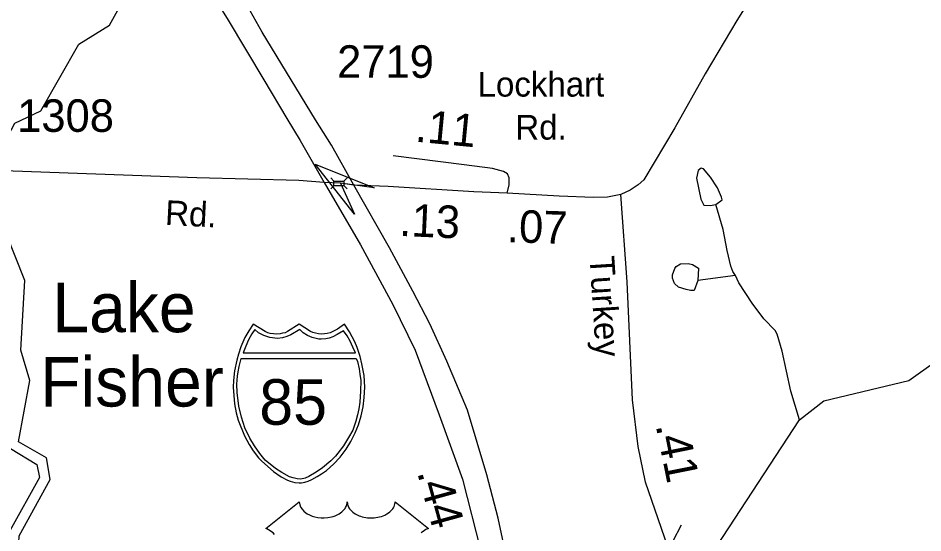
# Model space of a CAD drawing. Extents: x 1473865 to 1648260, y 639067 to 773536.
# Drawn here: x 1533158 to 1536635, y 642600 to 644578 of the extents above; entities that cross this region are included whole.
import ezdxf

# ---------------------------------------------------------------- set-up
doc = ezdxf.new("R2010")
doc.units = 0
for name, color, linetype in [('Exist Hydrographic Buffer Line', 7, 'Continuous'), ('Exist Hydrographic Creek Single Shore', 7, 'Continuous'), ('Exist Hydrographic Lake Shore', 7, 'Continuous'), ('Exist Hydrographic Lake Shore Label', 7, 'Continuous'), ('Exist Hydrographic Misc Water Feature', 7, 'Continuous'), ('Exist Road Primary Interstate Divided Center Attributed', 7, 'Continuous'), ('Exist Road Primary Interstate Mileage Hundredths English Label', 7, 'Continuous'), ('Exist Road Primary Interstate Shield CELL', 7, 'Continuous'), ('Exist Road Primary Interstate Shield Number Label', 7, 'Continuous'), ('Exist Road Primary US Shield CELL', 7, 'Continuous'), ('Exist Road Secondary Mileage Hundredths English Label', 7, 'Continuous'), ('Exist Road Secondary Structure Standard Bridge Attributed CELL', 7, 'Continuous'), ('Exist Road Secondary Structure Standard Bridge CELL', 7, 'Continuous'), ('Exist Road Secondary Type 51 Attributed', 7, 'Continuous'), ('Exist Road Secondary Type 51 Label', 7, 'Continuous'), ('Exist Road Secondary Type 51 Number Label', 7, 'Continuous')]:
    doc.layers.add(name, color=color, linetype=linetype)

msp = doc.modelspace()

# ---------------------------------------------------------------- linework, layer by layer
at = {"layer": 'Exist Hydrographic Buffer Line'}
msp.add_lwpolyline([(1533129.2, 642924.1), (1533230.8, 642863), (1533239.9, 642813), (1533126.9, 642608)], dxfattribs=at)
at = {"layer": 'Exist Hydrographic Creek Single Shore'}
for points in [[(1533145.9, 644174.4), (1533245.9, 644221.6), (1533391.9, 644477.9), (1533509.9, 644551.1), (1533586.9, 644690.7), (1533679.9, 644757.8), (1534047.8, 644842.2), (1534114.9, 644883.5), (1534310.9, 645122.5), (1534478.9, 645243.8), (1534666.9, 645476.4), (1534979.9, 645788.5), (1535526, 646046.6)], [(1536254.9, 643107.3), (1536580.9, 643186), (1536682.9, 643259.5), (1536786.3, 643339), (1536946.2, 643460.5), (1537173.9, 643751.8), (1537348.9, 643948.4), (1537493.2, 644144.8), (1537550.6, 644125.3), (1537590.8, 644111.1), (1537644.6, 644123.4), (1537654.1, 644129.7), (1537717.6, 644182.4), (1537698.9, 644286.1), (1537837.9, 644624.6), (1537981, 644713.7), (1538125.9, 644930.7), (1538234.9, 644987.6), (1538335, 645002), (1538509.9, 644939.3), (1538789, 644700.7), (1539004.9, 644624.1), (1539113, 644437.9)], [(1535821.8, 642516.4), (1536160.3, 643034.5), (1536254.9, 643107.3)]]:
    msp.add_lwpolyline(points, dxfattribs=at)
at = {"layer": 'Exist Hydrographic Lake Shore'}
msp.add_lwpolyline([(1533466.8, 641843.9), (1533442.8, 641867.4), (1533142.8, 641873.5), (1533049.9, 641826), (1532974.8, 641844), (1532967.8, 641932.8), (1533078.9, 642097.9), (1533149.8, 642332.8), (1533161.8, 642588.6), (1533281.9, 642806.1), (1533266.9, 642888.5), (1533159.9, 642949.8), (1533203.9, 643186.6), (1533168.5, 643302), (1533184.1, 643570.3), (1533111.9, 643751), (1533081.4, 643851), (1533050.8, 643978.9), (1532828.6, 643987.2), (1532834.9, 644062.5), (1533119.9, 644125.7), (1533145.9, 644174.4)], dxfattribs=at)
at = {"layer": 'Exist Hydrographic Misc Water Feature'}
msp.add_line((1535914.8, 643589.2), (1535770.7, 643570.8), dxfattribs=at)
for points in [[(1535839.1, 643862.4), (1535863.5, 643879.9), (1535861.6, 643889.8), (1535846.2, 643926.2), (1535818.9, 643967), (1535791.4, 643998.8), (1535783.4, 644001.4), (1535771.2, 643993.4), (1535764.9, 643963.2), (1535781.5, 643883.2), (1535793, 643859.2), (1535817, 643858.7), (1535839.1, 643862.4)], [(1535914.8, 643589.2), (1535905.1, 643605), (1535897.5, 643624.9), (1535882.3, 643685.9), (1535867.7, 643765.8), (1535839.1, 643862.4)], [(1535770.7, 643570.8), (1535755.9, 643531.7), (1535742, 643532), (1535726, 643535.6), (1535696.1, 643544.4), (1535680.4, 643558.7), (1535672.6, 643578.5), (1535672.8, 643592.5), (1535681.3, 643616.9), (1535687.4, 643624.2), (1535703.6, 643634.6), (1535733.6, 643635.6), (1535749.6, 643632), (1535773.3, 643617.5), (1535770.7, 643570.8)], [(1536160.3, 643034.5), (1536128, 643145.1), (1536094.4, 643298.4), (1536075.4, 643364.4), (1536067.7, 643378.5), (1536024.3, 643422.9), (1535979.1, 643483.7), (1535928.4, 643561.1), (1535914.8, 643589.2)]]:
    msp.add_lwpolyline(points, dxfattribs=at)
at = {"layer": 'Exist Road Primary Interstate Divided Center Attributed'}
for points in [[(1532067.3, 650189.8), (1532099.1, 649959.9), (1532111.6, 649897), (1532259.9, 649188.3), (1532318.9, 648953.8), (1532471.4, 648352.8), (1532570.8, 647967.9), (1532653.9, 647677.9), (1532722.1, 647429.7), (1532805, 647156.8), (1532938.2, 646804.3), (1533038.9, 646486.3), (1533121.3, 646291.5), (1533241.4, 645985.6), (1533539.8, 645344.6), (1533565.9, 645296.1), (1533841.5, 644771), (1533965.2, 644570.1), (1534102.5, 644341.3), (1534190.9, 644192.8), (1534242.1, 644107.9), (1534333.9, 643947.3)], [(1534448.8, 643936.4), (1534362.3, 644090.3), (1534300.4, 644187.5), (1534095.9, 644524.2), (1533991.7, 644709.8), (1533727.1, 645173.1), (1533476.4, 645676.2), (1533317.4, 646052.8), (1533114.9, 646555.3), (1533102.8, 646630.2), (1532913.8, 647168.1), (1532841.1, 647408.6), (1532674.2, 647927.5), (1532602.5, 648225.7), (1532357.1, 649178), (1532309.8, 649428.6), (1532208.2, 649864.6), (1532194.5, 649938.7), (1532161, 650159.7)], [(1534333.9, 643947.3), (1534473.6, 643706.6), (1534598.7, 643478.1), (1534683.6, 643303), (1534776.1, 643054.7), (1534865.6, 642806.9), (1534936.8, 642529.8), (1534978.3, 642275), (1535004.4, 642062.6), (1535011.1, 641823.7), (1535003.1, 641707.2)], [(1535103.8, 641702.9), (1535099.8, 641843.1), (1535091.6, 642021), (1535038.5, 642489), (1535003.2, 642656.5), (1534959.2, 642823.8), (1534885, 643071.4), (1534806, 643260.5), (1534740.5, 643403.7), (1534674.8, 643528.6), (1534584.9, 643695.9), (1534448.8, 643936.4)]]:
    msp.add_lwpolyline(points, dxfattribs=at)
at = {"layer": 'Exist Road Primary Interstate Shield CELL'}
for points in [[(1534237.9, 642792.2), (1534247.3, 642793.1), (1534260.1, 642795.6), (1534272.5, 642799.7), (1534286.6, 642805.9), (1534307.4, 642817.4), (1534324.2, 642827.3), (1534343.5, 642840.3), (1534369.6, 642864), (1534395.7, 642891.4), (1534418.7, 642922.4), (1534436.9, 642951.4), (1534453, 642984.6), (1534466.4, 643015.5), (1534477.1, 643050.8), (1534484.2, 643085.1), (1534487.7, 643120.8), (1534490.1, 643160.3), (1534487.4, 643204.9), (1534479.7, 643250.4), (1534472.4, 643278.8), (1534461.4, 643312.7), (1534452.4, 643334.4), (1534431.5, 643372.8), (1534412.8, 643402.4), (1534385.6, 643383.3), (1534367.8, 643373.8), (1534357, 643369), (1534345.8, 643366.8), (1534325.3, 643364.3), (1534312.4, 643364.9), (1534300.5, 643367.6), (1534290.4, 643369.8), (1534282.1, 643373.8), (1534237.9, 643402.4), (1534193.6, 643373.8), (1534184.3, 643369.6), (1534174.8, 643367.6), (1534165.7, 643365.1), (1534150.5, 643364.3), (1534139, 643364.7), (1534127.1, 643366.8), (1534117.7, 643368.8), (1534107.2, 643373.8), (1534062.1, 643402.4), (1534044.4, 643376.7), (1534029.9, 643351.3), (1534014.5, 643315.4), (1534005, 643287.6), (1533998.2, 643264.7), (1533989.8, 643222.7), (1533985.5, 643186.2), (1533984.8, 643160.3), (1533989.5, 643095.8), (1533996.5, 643061.5), (1534003.8, 643033.7), (1534027.6, 642973.6), (1534045.6, 642940), (1534061, 642915.9), (1534082.6, 642888.7), (1534094.3, 642875.7), (1534139.1, 642836.6), (1534169, 642816.1), (1534192.9, 642803.2), (1534204.1, 642798.9), (1534221.7, 642794)], [(1534067.4, 643381.7), (1534056.5, 643364.8), (1534043.8, 643341.9), (1534033.6, 643318.3), (1534023.3, 643292.1), (1534454.8, 643292), (1534444.8, 643314.4), (1534434, 643336.9), (1534422.8, 643357.5), (1534409.1, 643377.4), (1534384.9, 643362.1), (1534367.2, 643353.8), (1534353.1, 643348.9), (1534341.1, 643346.2), (1534322.5, 643344.7), (1534314.2, 643345.2), (1534288.2, 643351.1), (1534270.7, 643358.3), (1534254, 643369.4), (1534240.5, 643382.1), (1534206.3, 643361.5), (1534191.1, 643354.8), (1534173.6, 643350.3), (1534154.6, 643347.9), (1534125.1, 643351.1), (1534102.1, 643359.1), (1534082.2, 643369.4)], [(1534457.4, 643270.7), (1534462, 643258.5), (1534468.4, 643231.4), (1534471.7, 643210.6), (1534475.1, 643186.6), (1534473.9, 643145.5), (1534472, 643102.9), (1534468, 643077.7), (1534462.8, 643054.7), (1534455.6, 643029.3), (1534444.1, 642995.4), (1534428.2, 642966.8), (1534408.3, 642935), (1534386.9, 642907.1), (1534377.5, 642895.5), (1534359.8, 642876.9), (1534327.6, 642851), (1534304.1, 642833.4), (1534275.9, 642816.8), (1534261.6, 642810.4), (1534244.9, 642806.9), (1534231.2, 642807.9), (1534214.6, 642812.3), (1534201.1, 642816), (1534171.7, 642831.9), (1534147.9, 642847.8), (1534108.1, 642880.4), (1534086.6, 642905.6), (1534066.6, 642934.9), (1534048.7, 642965), (1534029.6, 643004.7), (1534016.2, 643044.6), (1534006.4, 643087.7), (1533999.8, 643140.3), (1533999.1, 643172.4), (1534001, 643203.2), (1534004, 643219.4), (1534007.9, 643239.5), (1534015.7, 643270.4)]]:
    msp.add_lwpolyline(points, close=True, dxfattribs=at)
at = {"layer": 'Exist Road Primary US Shield CELL'}
msp.add_lwpolyline([(1534143.5, 642594.8), (1534137.8, 642600.5), (1534132.3, 642604.8), (1534127.1, 642608.5), (1534120.6, 642612.5), (1534114.3, 642615.6), (1534110.3, 642617.2), (1534238.9, 642719.6), (1534239.2, 642714.3), (1534240.5, 642708), (1534241.5, 642704.7), (1534244.5, 642698.5), (1534249.3, 642691.1), (1534256.1, 642683.9), (1534263.8, 642677.6), (1534269, 642674.2), (1534277.7, 642669.5), (1534287.7, 642665.3), (1534298.8, 642662.2), (1534310.1, 642659.9), (1534322.5, 642658.5), (1534334.7, 642658.3), (1534347.9, 642659.3), (1534362.5, 642662.1), (1534369.2, 642663.8), (1534376.8, 642666.4), (1534383.8, 642669.3), (1534391.4, 642673.4), (1534397.6, 642677.4), (1534402.4, 642680.8), (1534409.2, 642687.4), (1534414.7, 642694.1), (1534416.9, 642697.9), (1534418.9, 642701.6), (1534421.6, 642709.3), (1534422.4, 642712.8), (1534422.9, 642719.9), (1534423.4, 642713.9), (1534424, 642710.2), (1534425, 642706.5), (1534426.5, 642702.7), (1534429.2, 642697.2), (1534432.2, 642692.6), (1534438, 642685.9), (1534441.5, 642682.5), (1534444.8, 642679.9), (1534453.5, 642673.9), (1534463.8, 642668.7), (1534468.8, 642666.5), (1534473.9, 642664.7), (1534480.5, 642662.7), (1534487.2, 642661.1), (1534493.9, 642660), (1534500.7, 642659), (1534507.7, 642658.4), (1534513.4, 642658.3), (1534520.4, 642658.4), (1534526.9, 642658.7), (1534533.5, 642659.5), (1534540.8, 642660.7), (1534546.6, 642662), (1534554.4, 642664.1), (1534561.4, 642666.6), (1534567.5, 642669.2), (1534575.5, 642673.4), (1534581.9, 642677.4), (1534586.7, 642681.2), (1534592.3, 642686.4), (1534597.6, 642692.6), (1534600.7, 642697), (1534602.9, 642701.7), (1534605, 642706.5), (1534606.2, 642711.7), (1534606.8, 642716.2), (1534606.9, 642720), (1534735.5, 642617.6), (1534732.5, 642616.4), (1534725.5, 642613), (1534720, 642609.7), (1534711.1, 642603.5), (1534707.3, 642600.1)], dxfattribs=at)
at = {"layer": 'Exist Road Secondary Structure Standard Bridge Attributed CELL'}
msp.add_lwpolyline([(1534450.7, 643824.9), (1534300, 644016.6), (1534526.4, 643925.9), (1534397.6, 643943.5)], close=True, dxfattribs=at)
at = {"layer": 'Exist Road Secondary Structure Standard Bridge CELL'}
for p, q in [((1534359.9, 643964.1), (1534372.1, 643951.9)), ((1534409.9, 643951.8), (1534422.1, 643964)), ((1534359.9, 643922), (1534372.1, 643934.2)), ((1534409.9, 643934.5), (1534422.1, 643922.3)), ((1535676, 642569.6), (1535706.9, 642631.3))]:
    msp.add_line(p, q, dxfattribs=at)
msp.add_lwpolyline([(1534372.1, 643951.9), (1534409.9, 643951.9), (1534409.9, 643934.2), (1534372.1, 643934.2)], close=True, dxfattribs=at)
at = {"layer": 'Exist Road Secondary Type 51 Attributed'}
for points in [[(1536846.3, 645558.6), (1536759.1, 645492.3), (1536578.3, 645352.6), (1536423.9, 645210.7), (1536271.6, 645062.7), (1536131.8, 644906.5), (1535919.8, 644569.2), (1535798, 644364), (1535682.3, 644156.4), (1535562.6, 643956.3), (1535540.4, 643937.5), (1535510.5, 643917.6), (1535474, 643901)], [(1535037.8, 643905.4), (1535045.5, 643937.5), (1535045.5, 643964.1), (1535038.9, 643979.6), (1535023.4, 643988.4), (1534981.3, 644000.6), (1534871.7, 644015), (1534599.3, 644049.3)], [(1534333.9, 643947.3), (1534236.8, 643954.1), (1533844.6, 643964.7), (1532749.8, 644003.8)], [(1534448.8, 643936.4), (1534397.6, 643943.5), (1534333.9, 643947.3)], [(1535037.8, 643905.4), (1534909.4, 643910.6), (1534580.5, 643930.9), (1534448.8, 643936.4)], [(1535474, 643901), (1535423.1, 643889.9), (1535369.9, 643888.8), (1535237, 643894.3), (1535037.8, 643905.4)], [(1535679.6, 642476.1), (1535568.7, 642795.4), (1535541.2, 642932), (1535518.7, 643112.3), (1535498.3, 643565.5), (1535474, 643901)]]:
    msp.add_lwpolyline(points, dxfattribs=at)

# ---------------------------------------------------------------- texts
at = {"layer": 'Exist Hydrographic Lake Shore Label'}
for s, p in [('Lake', (1533289.6, 643371.5)), ('Fisher', (1533242.8, 643086))]:
    msp.add_text(s, height=190, dxfattribs=at).set_placement(p)
at = {"layer": 'Exist Road Primary Interstate Mileage Hundredths English Label'}
msp.add_text('.44', height=125, rotation=285.4032, dxfattribs=at).set_placement((1534691, 642833.5))
at = {"layer": 'Exist Road Primary Interstate Shield Number Label'}
msp.add_text('85', height=175, dxfattribs=at).set_placement((1534085, 643016))
at = {"layer": 'Exist Road Secondary Mileage Hundredths English Label'}
for s, rotation, p in [('.11', 354.5525, (1534681.3, 644104)), ('.13', 357.4552, (1534621.6, 643741.7)), ('.07', 358.2077, (1535035.2, 643717.7)), ('.41', 281.3636, (1535608, 643013.9))]:
    msp.add_text(s, height=125, rotation=rotation, dxfattribs=at).set_placement(p)
at = {"layer": 'Exist Road Secondary Type 51 Label'}
for s, p in [('Lockhart', (1534923.8, 644276.7)), ('Rd.', (1535068.7, 644111.5))]:
    msp.add_text(s, height=95, dxfattribs=at).set_placement(p)
for s, rotation, p in [('Rd.', 357.1425, (1533721.4, 643783.9)), ('Turkey', 273.6237, (1535354, 643661.9))]:
    msp.add_text(s, height=95, rotation=rotation, dxfattribs=at).set_placement(p)
at = {"layer": 'Exist Road Secondary Type 51 Number Label'}
for s, p in [('2719', (1534384.1, 644348.8)), ('1308', (1533154.6, 644141.2))]:
    msp.add_text(s, height=125, dxfattribs=at).set_placement(p)

doc.saveas('drawing.dxf')
